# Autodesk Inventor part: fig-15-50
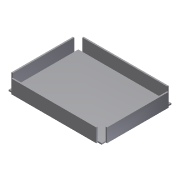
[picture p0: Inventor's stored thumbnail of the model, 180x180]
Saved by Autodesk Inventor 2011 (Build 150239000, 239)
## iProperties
Shininess: 77.0
Angle Display Precision: 2
Document Length Units: 11269
Document Angle Units: 11279
Document Time Units: 11290
Document Mass Units: 11283
Document Length Units Precision: 3
Document Angle Units Precision: 2
Compacted: True
Created: 2002-04
Part Number: fig-15-50
Document SubType Name: Sheet Metal
Density: 1 g/cm^3
Sheet Metal Rule: Default
Density: 0.0
Volumn: 0.0
Area: 0.0
PropertySet Name: Model Information
Control State: 0
Master: False
Checked Out: False
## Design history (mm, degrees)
sketch "Sketch1"
  geometry: L1 (-34, 28)-(36, 28); L2 (36, 28)-(36, -24.941); L3 (36, -24.941)-(-34, -24.941); L4 (-34, -24.941)-(-34, 28)
  constraints: 8 end point, 2 parallel, 1 horizontal, 1 perpendicular
extrude "Extrusion1" join sketch "Sketch1" distance "d0" = 10; taper "d1" = 0 deg
shell "Shell1" dims "d2" = 1
feature "Corner9" dims "d27" = 4 (= CornerReliefSize), "d28" = 1 (= BendRadius), "d29" = 3, "d30" = 0, "d31" = 10, "Thickness" = 1
feature "Corner10" dims "d32" = 4 (= CornerReliefSize), "d33" = 1 (= BendRadius), "d34" = 3, "d35" = 0, "d36" = 10, "Thickness" = 1
body "Solid1"
other parameters: "BendRadius" = 1 (= Thickness), "BendReliefWidth" = 1 (= Thickness), "BendReliefDepth" = 0.5 (= 0.5 x Thickness), "CornerReliefSize" = 4 (= 4 x Thickness), "SeamGap" = 0.01, "MinimumRemnant" = 2 (= 2 x Thickness), "TransitionRadius" = 1 (= BendRadius), "JacobiRadiusSize" = 1 (= Thickness), "GapSize" = 1 (= Thickness)
